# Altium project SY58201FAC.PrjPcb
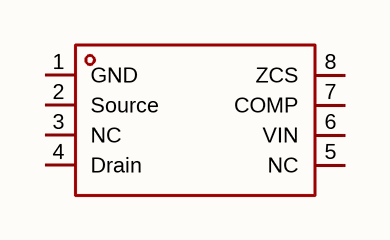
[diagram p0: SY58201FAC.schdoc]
1 sheet, 1 parts. Net scope: global (net labels, ports and power ports of the same name join across sheets).

## Sheet SY58201FAC.schdoc
size 127 x 101 mm

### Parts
U?  sy58201fac  [SO-8_L4.9-W3.9-P1.27-LS6.0-BL]  (value not drawn)

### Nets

Not connected (* = marked no-connect by the designer): U? 1(GND) 2(Source) 3(NC) 4(Drain) 5(NC) 6(VIN) 7(COMP) 8(ZCS)

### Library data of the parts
U? = sy58201fac: 类型:AC-DC;工作电压(DC):-;开关频率:120kHz;通道数:1;输出电压:-;输出电流:-;调光:-;拓扑结构:反激;; Manufacturer: Silergy(矽力杰); AddInBom: yes; ModelId: 50ce3402a2354e6c8e8bd1c9ad02453e; ModelTransform: 192.913,236.22,0,0,0,0,0,0,0; Frequency - Switching: 120kHz; Number of Channels: 1; Voltage - Input(AC): 90VAC~264VAC; Topology: 反激; Switch Tube (Built-In/External): 内置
